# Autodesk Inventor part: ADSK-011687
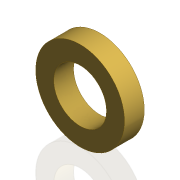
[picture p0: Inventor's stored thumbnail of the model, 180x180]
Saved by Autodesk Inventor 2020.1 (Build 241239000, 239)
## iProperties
Created: 2000-02
Part Number: ADSK-011687
Material: Générique
Document SubType Name: Modeling
Description: PLT-01,SY,CP,05,021,BUMPER
Designer: sspink
Density: 1 g/cm^3
Appearance: Vorgabe
Mass: 17.8317 g
Surface Area: 62.1407 cm^2
Volume: 17.8317 cm^3
Control State: 0
Checked Out: False
Master: False
Shininess: 20.0
Length Units: 11269
Angle Units: 11279
Time Units: 11290
Mass Units: 11283
Length Display Precision: 3
Angle Display Precision: 2
Compacted: True
Cutlength: 2.25 X 2.25 (5 SI)
Material Desc: SHEET,URETHANE,0.50 THK 60A
Material_Number: A105234
Dimensions: 54x54x12 mm
Mass: 0,018 kg
DocNumber: ADSK-011687.ipt
Folder: 01 - Themengebiete\Simplification\01 - Packaging machine\
VDS_Category: 3D Komponenten
Density: 1.0
Volumn: 19.084184590146542
Area: 64.20591809140213
PropertySet Name: Model Information
Author: sspink
Revision Number: -
Title: PLT-01,SY,CP,05,021,BUMPER
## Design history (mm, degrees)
node "Solide1"
  node "Extrusion1" dims "d2" = 12, "d3" = 0
sketch "Sketch1"
  geometry: C1 r 16 at (0, 0); C2 r 27 at (0, 0); 1 further point
  constraints: 2 centre point, 2 coincident
  dimensions: "d0" = 32 diameter of C1; "d1" = 54 diameter of C2
node "Corps solides"
node "Corps surfaciques"
